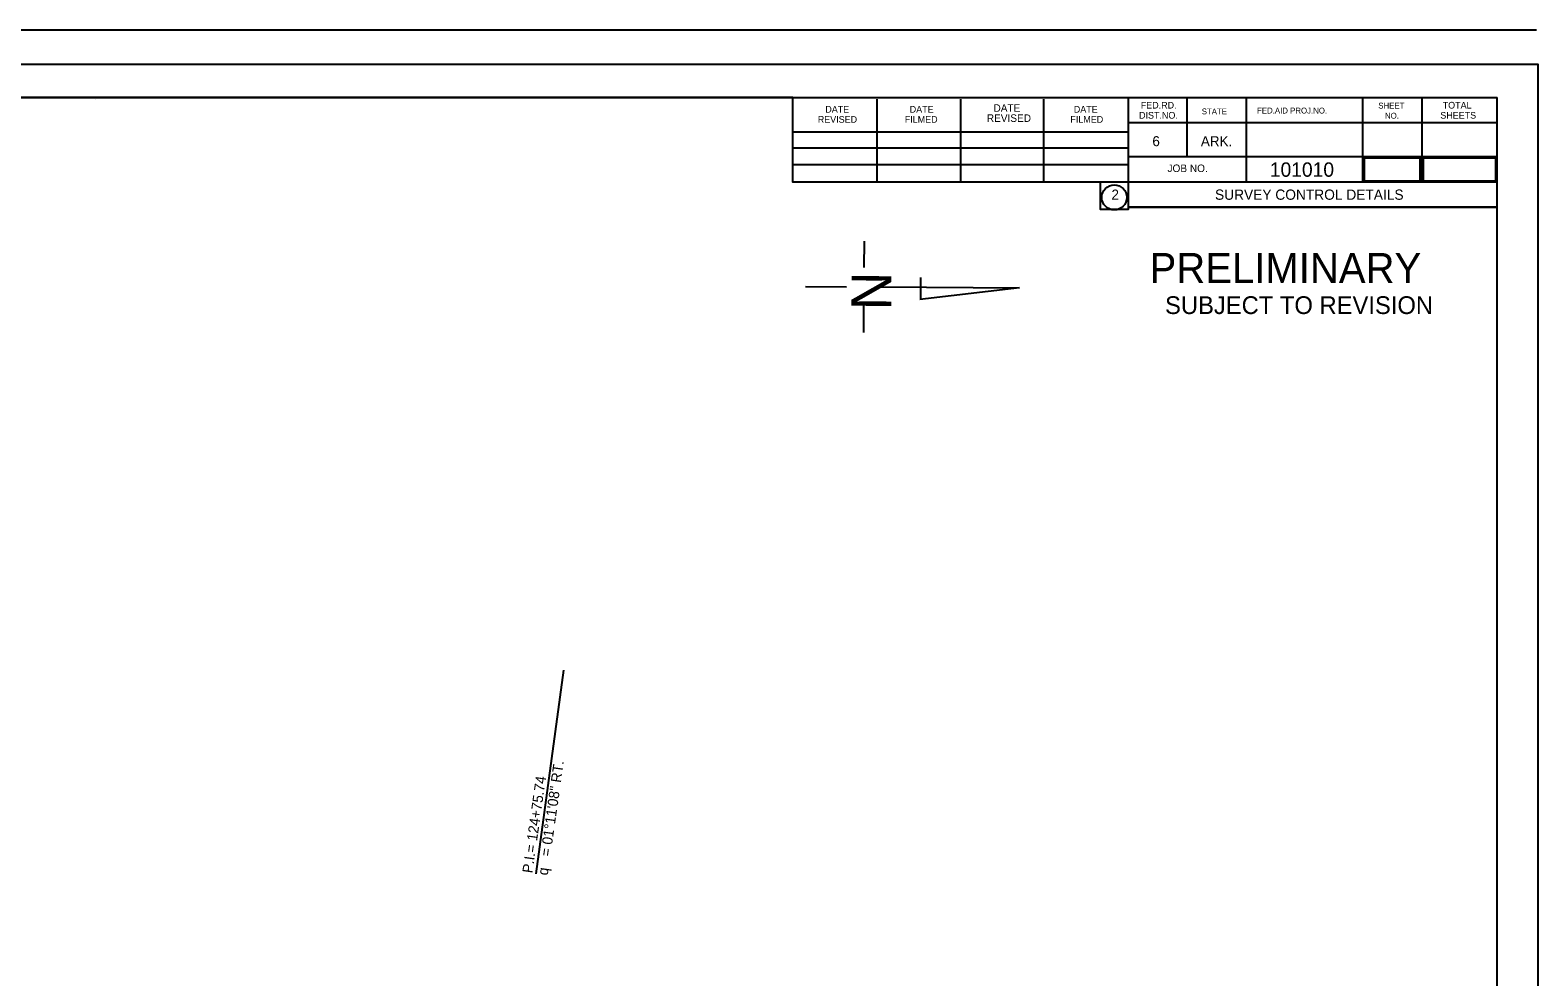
# Model space of a CAD drawing. Extents: x 3698 to 9589, y 10000 to 11106.
# Drawn here: x 8709 to 9589, y 10553 to 11106 of the extents above; entities that cross this region are included whole.
import ezdxf

# ---------------------------------------------------------------- set-up
doc = ezdxf.new("R2010")
doc.units = 0
for name, color, linetype in [('DATE', 7, 'Continuous'), ('GREEN_TXT', 7, 'Continuous'), ('R_Clearzone', 7, 'Continuous'), ('R_Culvert', 7, 'Continuous'), ('R_Driveway Slope', 7, 'Continuous'), ('R_Vert Alg LP', 7, 'Continuous'), ('RC Box Annot', 7, 'Continuous'), ('SEAL-INFO', 7, 'Continuous')]:
    doc.layers.add(name, color=color, linetype=linetype)

msp = doc.modelspace()

# ---------------------------------------------------------------- linework, layer by layer
for p, q in [((9195.47, 10982.92), (9195.36, 10967.49)), ((9228.51, 10961.58), (9228.42, 10948.65)), ((9161.23, 10956.4), (9185.15, 10956.24)), ((9204.87, 10956.1), (9286.22, 10955.54)), ((9286.22, 10955.54), (9227.99, 10948.66)), ((9195.21, 10945.9), (9195.1, 10929.41))]:
    msp.add_line(p, q)
at = {"layer": 'DATE'}
msp.add_lwpolyline([(7984.24, 11066.7), (7984.24, 10039.4), (9565.14, 10039.4), (9565.14, 11002.7), (9349.64, 11002.7), (9349.64, 11001.26), (9333.45, 11001.26), (9333.45, 11017.3), (9153.84, 11017.3), (9153.84, 11066.7)], close=True, dxfattribs=at)
msp.add_lwpolyline([(7984.24, 11066.7), (7984.24, 10039.4), (9565.14, 10039.4), (9565.14, 11002.7), (9349.64, 11002.7), (9349.64, 11001.26), (9333.45, 11001.26), (9333.45, 11017.3), (9153.84, 11017.3), (9153.84, 11066.7)], close=True, dxfattribs=at)
at = {"layer": 'GREEN_TXT'}
for p, q in [((9588.14, 11106.1), (7828.14, 11106.1)), ((7984.24, 11066.7), (9565.14, 11066.7)), ((9153.84, 11017.3), (9153.84, 11066.7)), ((9349.64, 11066.7), (9349.64, 11002.7)), ((9383.84, 11066.7), (9383.84, 11032)), ((9418.54, 11066.7), (9418.54, 11017.3)), ((9486.44, 11066.7), (9486.44, 11017.3)), ((9521.14, 11066.7), (9521.14, 11017.3)), ((9565.14, 10039.4), (9565.14, 11066.7)), ((8746.84, 11065.4), (8746.84, 11065.4)), ((8746.84, 11065.4), (8746.84, 11065.4)), ((9203.14, 11017.3), (9203.14, 11065.7)), ((9251.94, 11017.3), (9251.94, 11065.7)), ((9300.34, 11017.3), (9300.34, 11065.7)), ((9565.14, 11052), (9349.64, 11052)), ((9565.14, 11052.1), (9565.14, 11052.1)), ((9153.84, 11046.6), (9349.64, 11046.6)), ((9153.84, 11037.3), (9349.64, 11037.3)), ((9565.14, 11032), (9349.64, 11032)), ((9153.84, 11027.6), (9349.64, 11027.6)), ((9565.14, 11017.3), (9153.84, 11017.3)), ((9349.64, 11002.7), (9565.14, 11002.7))]:
    msp.add_line(p, q, dxfattribs=at)
msp.add_circle((9341.57, 11008.38), 7.33, dxfattribs=at)
at = {"layer": 'R_Clearzone'}
msp.add_lwpolyline([(7922.2, 11086.17), (9588.9, 11086.17), (9588.9, 10019.49), (7922.2, 10019.49)], close=True, dxfattribs=at)
at = {"layer": 'R_Culvert'}
msp.add_lwpolyline([(9019.9, 10732.17), (9003.88, 10613.24)], dxfattribs=at)
at = {"layer": 'R_Driveway Slope'}
msp.add_lwpolyline([(9521.96, 11018.05), (9564.32, 11018.05), (9564.32, 11031.25), (9521.96, 11031.25)], close=True, dxfattribs=at)
at = {"layer": 'RC Box Annot'}
msp.add_lwpolyline([(9487.46, 11018.05), (9520.12, 11018.05), (9520.12, 11031.25), (9487.46, 11031.25)], close=True, dxfattribs=at)

# ---------------------------------------------------------------- texts
msp.add_text('N', height=23.27, rotation=269.60618).set_placement((9188.17, 10965.04))
at = {"layer": 'GREEN_TXT'}
for s, height, p in [('DATE', 3.91, (9172.84, 11057.9)), ('DATE', 3.91, (9222.14, 11057.9)), ('DATE', 4.396, (9271.04, 11058.4)), ('DATE', 3.91, (9317.94, 11057.9)), ('DIST.NO.', 3.91, (9356.04, 11054.4)), ('FED.RD.', 3.91, (9357.04, 11060.3)), ('STATE', 3.42, (9392.64, 11056.9)), ('FED.AID PROJ.NO.', 3.42, (9424.94, 11057.4)), ('SHEET', 3.42, (9495.74, 11060.3)), ('NO.', 3.42, (9499.64, 11054.4)), ('SHEETS', 3.91, (9531.94, 11054.4)), ('TOTAL', 3.91, (9533.34, 11060.3)), ('REVISED', 3.91, (9168.44, 11052)), ('FILMED', 3.91, (9219.24, 11052)), ('REVISED', 4.396, (9267.14, 11052.5)), ('FILMED', 3.91, (9315.94, 11052)), ('6', 5.86, (9363.84, 11038.3)), ('ARK.', 5.861, (9392.14, 11038.3)), ('JOB NO.', 4.396, (9372.64, 11023.2)), ('2', 5.86, (9339.94, 11007.1))]:
    msp.add_text(s, height=height, dxfattribs=at).set_placement(p)
at = {"layer": 'R_Culvert'}
for s, p in [('q   = 01%%d11\'08" RT.', (9010.7, 10612.1)), ('P.I.= 124+75.74', (9001.79, 10613.37))]:
    msp.add_text(s, height=6, rotation=81.87234, dxfattribs=at).set_placement(p)
at = {"layer": 'R_Vert Alg LP'}
for s, height, p in [('101010', 8.4, (9432.42, 11020.45)), ('SURVEY CONTROL DETAILS', 6, (9400.39, 11007))]:
    msp.add_text(s, height=height, dxfattribs=at).set_placement(p)
at = {"layer": 'SEAL-INFO'}
for s, height, p in [('PRELIMINARY', 17.5, (9362.17, 10958.41)), ('SUBJECT TO REVISION', 10.3756, (9371.22, 10940.26))]:
    msp.add_text(s, height=height, dxfattribs=at).set_placement(p)

doc.saveas('drawing.dxf')
